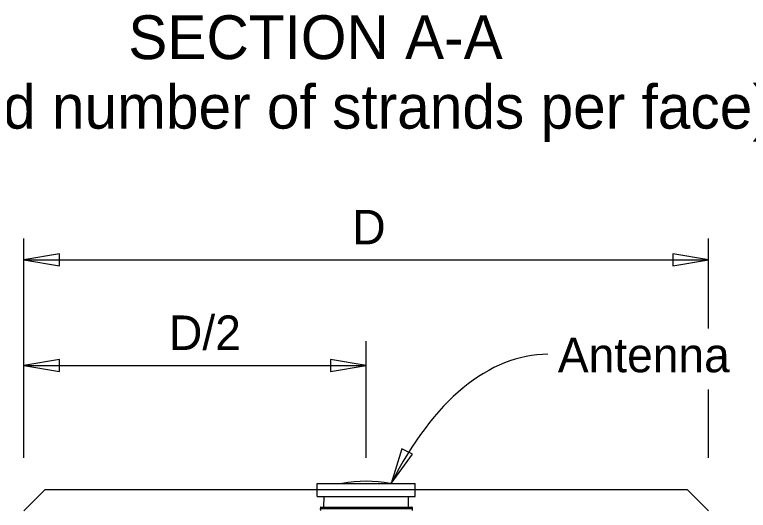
# Model space of a CAD drawing. Extents: x 0 to 36.1, y -3.7 to 15.
# Drawn here: x 2.266 to 4.409, y 4.351 to 5.799 of the extents above; entities that cross this region are included whole.
import ezdxf

# ---------------------------------------------------------------- set-up
doc = ezdxf.new("R2010")
doc.units = 0
for name, color, linetype in [('Dimension', 7, 'Continuous'), ('Leader', 7, 'Continuous'), ('Miscellaneous', 7, 'Continuous'), ('PileConc', 7, 'Continuous'), ('TextStructures', 7, 'Continuous')]:
    doc.layers.add(name, color=color, linetype=linetype)

msp = doc.modelspace()

# ---------------------------------------------------------------- linework, layer by layer
at = {"layer": 'Dimension'}
for p, q in [((2.293, 4.5036), (2.293, 5.1448)), ((4.293, 4.8819), (4.293, 5.1448)), ((2.293, 5.083), (4.293, 5.083)), ((3.293, 4.5036), (3.293, 4.8451)), ((2.293, 4.7742), (3.293, 4.7742)), ((4.293, 4.5036), (4.293, 4.7034))]:
    msp.add_line(p, q, dxfattribs=at)
for points in [[(2.293, 5.083), (2.3972, 5.0654), (2.3972, 5.1006)], [(4.293, 5.083), (4.1889, 5.1006), (4.1889, 5.0654)], [(2.293, 4.7742), (2.3972, 4.7566), (2.3972, 4.7918)], [(3.293, 4.7742), (3.1889, 4.7918), (3.1889, 4.7566)], [(3.3658, 4.4293), (3.4285, 4.5143), (3.397, 4.5302)]]:
    msp.add_lwpolyline(points, close=True, dxfattribs=at)
at = {"layer": 'Leader'}
msp.add_ellipse((3.8235, 3.4979), major_axis=(0, -1.3086), ratio=0.497877, start_param=3.141593, end_param=3.920397, dxfattribs=at)
at = {"layer": 'Miscellaneous'}
for p, q in [((3.1499, 4.4293), (3.1915, 4.4293)), ((3.1499, 4.4118), (3.1499, 4.4293)), ((3.1915, 4.4293), (3.3946, 4.4293)), ((3.2228, 4.4294), (3.2228, 4.4293)), ((3.3633, 4.4294), (3.3633, 4.4293)), ((3.3946, 4.4293), (3.4362, 4.4293)), ((3.4362, 4.4118), (3.4362, 4.4293)), ((3.1499, 4.391), (3.1499, 4.4118)), ((3.1499, 4.4118), (3.1915, 4.4118)), ((3.1915, 4.4118), (3.3946, 4.4118)), ((3.3946, 4.4118), (3.4362, 4.4118)), ((3.4362, 4.391), (3.4362, 4.4118)), ((3.1499, 4.391), (3.1915, 4.391)), ((3.1693, 4.361), (3.1701, 4.391)), ((3.1915, 4.391), (3.3946, 4.391)), ((3.3946, 4.391), (3.4362, 4.391)), ((3.4167, 4.361), (3.416, 4.391)), ((3.159, 4.3585), (3.1589, 4.3545)), ((3.1915, 4.3545), (3.1589, 4.3545)), ((3.1589, 4.3545), (3.159, 4.3505)), ((3.1603, 4.3597), (3.1915, 4.3597)), ((3.1915, 4.3597), (3.3946, 4.3597)), ((3.3946, 4.3545), (3.1915, 4.3545)), ((3.3946, 4.3597), (3.4258, 4.3597)), ((3.4272, 4.3545), (3.3946, 4.3545)), ((3.4271, 4.3585), (3.4272, 4.3545)), ((3.4272, 4.3545), (3.4271, 4.3505))]:
    msp.add_line(p, q, dxfattribs=at)
for centre, radius, start, end in [((3.293, 4.0317), 0.4038, 79.9853, 100.0147), ((3.293, 4.0317), 0.4038, 100.0147, 100.0917), ((3.293, 4.0317), 0.4038, 79.9083, 79.9853), ((3.1603, 4.3585), 0.00125, 90, 178.5), ((3.1681, 4.361), 0.00125, 270, 358.5), ((3.418, 4.361), 0.00125, 181.5, 270), ((3.4258, 4.3585), 0.00125, 1.5, 90)]:
    msp.add_arc(centre, radius, start, end, dxfattribs=at)
at = {"layer": 'PileConc'}
for p, q in [((2.293, 4.3493), (2.3555, 4.4118)), ((2.3555, 4.4118), (4.2305, 4.4118)), ((4.2305, 4.4118), (4.293, 4.3493))]:
    msp.add_line(p, q, dxfattribs=at)

# ---------------------------------------------------------------- texts
at = {"layer": 'Dimension'}
msp.add_text('Antenna', height=0.1008, dxfattribs=at).set_placement((3.8526, 4.7541))
at = {"layer": 'TextStructures'}
for s, height, p in [('SECTION A-A', 0.128, (2.598, 5.6693)), ('(Strand Pattern with odd number of strands per face)', 0.128, (0.4817, 5.4661)), ('D', 0.1008, (3.2524, 5.128)), ('D/2', 0.1008, (2.7171, 4.8192))]:
    msp.add_text(s, height=height, dxfattribs=at).set_placement(p)

doc.saveas('drawing.dxf')
